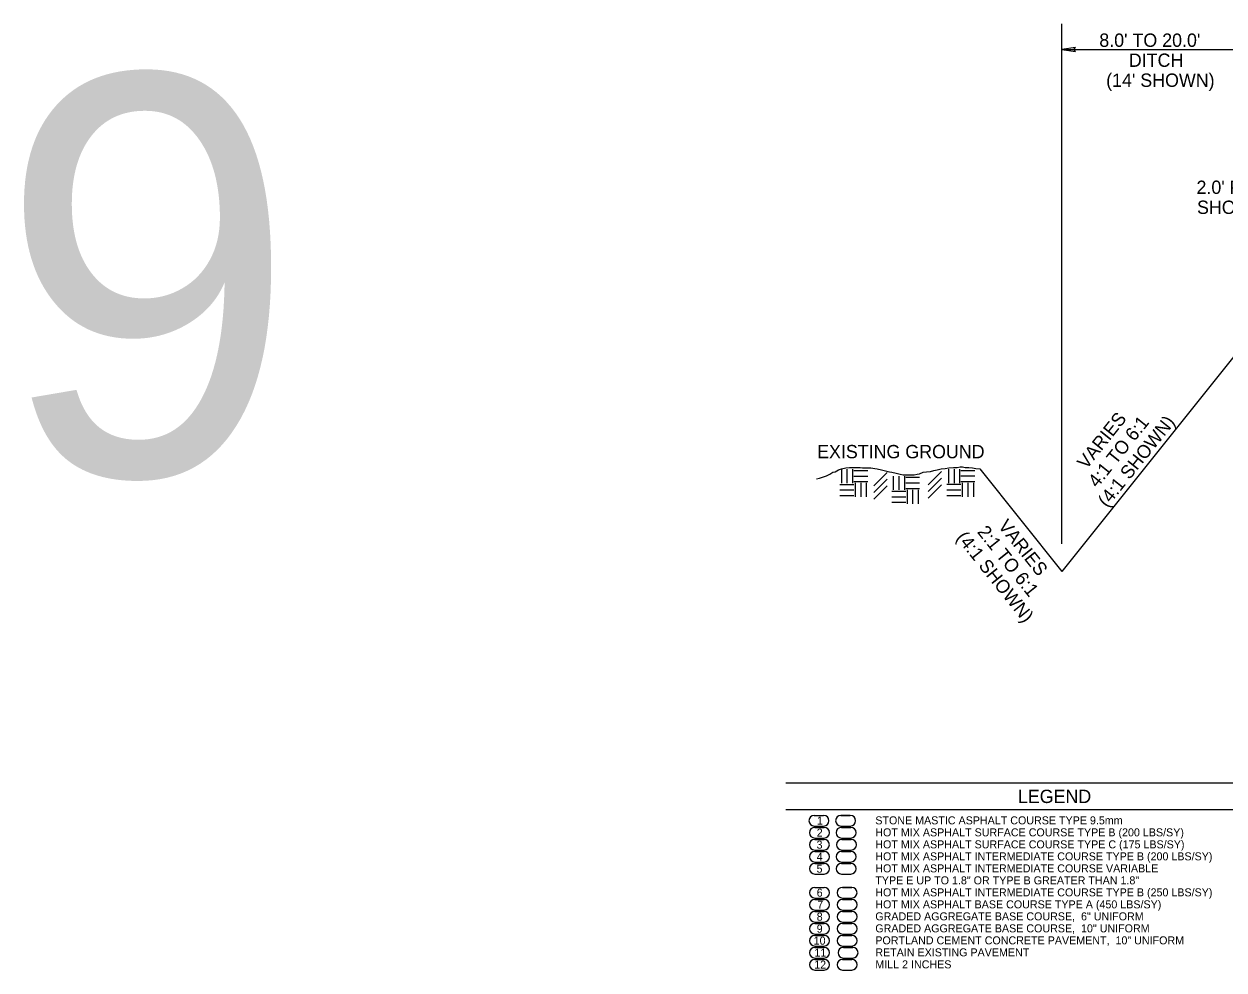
# Model space of a CAD drawing. Extents: x 2003207 to 2014043, y 843846 to 860154.
# Drawn here: x 2013558.6 to 2013648.6, y 843966.4 to 844037.3 of the extents above; entities that cross this region are included whole.
import ezdxf

# ---------------------------------------------------------------- set-up
doc = ezdxf.new("R2010")
doc.units = 0
for name, color, linetype in [('RD_EX_Road', 7, 'Continuous'), ('RD_EX_Road_txCode', 7, 'Continuous'), ('RD_QTY_ConcPave', 7, 'Continuous'), ('RD_QTY_Intermediate', 7, 'Continuous'), ('RD_QTY_Milling', 7, 'Continuous'), ('RD_QTY_PermVeg', 7, 'Continuous'), ('RD_QTY_Surf_Course', 7, 'Continuous'), ('RD_SHT_Bndy', 7, 'Continuous'), ('RD_SHT_TX', 7, 'Continuous'), ('RD_TX_Misc2', 7, 'Continuous'), ('RD_TX_TypSect', 7, 'Continuous'), ('RD_XS_ExGround', 7, 'Continuous')]:
    doc.layers.add(name, color=color, linetype=linetype)

msp = doc.modelspace()

# ---------------------------------------------------------------- linework, layer by layer
at = {"layer": 'RD_EX_Road'}
for p, q in [((2013620.723, 843968.087), (2013620.023, 843968.087)), ((2013620.661, 843967.187), (2013619.961, 843967.187)), ((2013620.023, 843967.287), (2013620.723, 843967.287)), ((2013619.961, 843966.387), (2013620.661, 843966.387))]:
    msp.add_line(p, q, dxfattribs=at)
for centre, start, end in [((2013620.023, 843967.687), 90, 270), ((2013620.723, 843967.687), 270, 90), ((2013619.961, 843966.787), 90, 270), ((2013620.661, 843966.787), 270, 90)]:
    msp.add_arc(centre, 0.4, start, end, dxfattribs=at)
at = {"layer": 'RD_EX_Road_txCode'}
msp.add_lwpolyline([(2013636.392, 844035.433), (2013637.431, 844035.283), (2013637.271, 844035.433), (2013637.431, 844035.583)], close=True, dxfattribs=at)
at = {"layer": 'RD_QTY_ConcPave'}
for p, q in [((2013620.661, 843970.787), (2013619.961, 843970.787)), ((2013619.961, 843969.987), (2013620.661, 843969.987)), ((2013620.661, 843969.887), (2013619.961, 843969.887)), ((2013619.961, 843969.087), (2013620.661, 843969.087)), ((2013620.661, 843968.987), (2013619.961, 843968.987)), ((2013619.961, 843968.187), (2013620.661, 843968.187))]:
    msp.add_line(p, q, dxfattribs=at)
for centre, start, end in [((2013619.961, 843970.387), 90, 270), ((2013620.661, 843970.387), 270, 90), ((2013619.961, 843969.487), 90, 270), ((2013620.661, 843969.487), 270, 90), ((2013619.961, 843968.587), 90, 270), ((2013620.661, 843968.587), 270, 90)]:
    msp.add_arc(centre, 0.4, start, end, dxfattribs=at)
at = {"layer": 'RD_QTY_Intermediate'}
for p, q in [((2013620.582, 843975.287), (2013619.882, 843975.287)), ((2013619.882, 843974.487), (2013620.582, 843974.487)), ((2013620.582, 843974.387), (2013619.882, 843974.387)), ((2013619.882, 843973.587), (2013620.582, 843973.587)), ((2013620.65, 843972.587), (2013619.95, 843972.587)), ((2013619.95, 843971.787), (2013620.65, 843971.787)), ((2013620.661, 843971.687), (2013619.961, 843971.687)), ((2013619.961, 843970.887), (2013620.661, 843970.887))]:
    msp.add_line(p, q, dxfattribs=at)
for centre, start, end in [((2013619.882, 843974.887), 90, 270), ((2013620.582, 843974.887), 270, 90), ((2013619.882, 843973.987), 90, 270), ((2013620.582, 843973.987), 270, 90), ((2013619.95, 843972.187), 90, 270), ((2013620.65, 843972.187), 270, 90), ((2013619.961, 843971.287), 90, 270), ((2013620.661, 843971.287), 270, 90)]:
    msp.add_arc(centre, 0.4, start, end, dxfattribs=at)
at = {"layer": 'RD_QTY_Milling'}
for p, q in [((2013620.661, 843967.187), (2013619.961, 843967.187)), ((2013619.961, 843966.387), (2013620.661, 843966.387))]:
    msp.add_line(p, q, dxfattribs=at)
for centre, start, end in [((2013619.961, 843966.787), 90, 270), ((2013620.661, 843966.787), 270, 90)]:
    msp.add_arc(centre, 0.4, start, end, dxfattribs=at)
at = {"layer": 'RD_QTY_PermVeg'}
for p in [(2013650.392, 844013.786), (2013630.245, 844003.97)]:
    msp.add_line(p, (2013636.392, 843996.286), dxfattribs=at)
at = {"layer": 'RD_QTY_Surf_Course'}
for p, q in [((2013620.542, 843977.987), (2013619.842, 843977.987)), ((2013619.842, 843977.187), (2013620.542, 843977.187)), ((2013620.576, 843977.087), (2013619.876, 843977.087)), ((2013619.876, 843976.287), (2013620.576, 843976.287)), ((2013620.61, 843976.187), (2013619.91, 843976.187)), ((2013619.91, 843975.387), (2013620.61, 843975.387))]:
    msp.add_line(p, q, dxfattribs=at)
for centre, start, end in [((2013619.842, 843977.587), 90, 270), ((2013620.542, 843977.587), 270, 90), ((2013619.876, 843976.687), 90, 270), ((2013620.576, 843976.687), 270, 90), ((2013619.91, 843975.787), 90, 270), ((2013620.61, 843975.787), 270, 90)]:
    msp.add_arc(centre, 0.4, start, end, dxfattribs=at)
at = {"layer": 'RD_SHT_Bndy'}
for p, q in [((2013655.72, 843980.41), (2013615.72, 843980.41)), ((2013655.72, 843978.41), (2013615.72, 843978.41))]:
    msp.add_line(p, q, dxfattribs=at)
at = {"layer": 'RD_TX_Misc2'}
for p, q in [((2013617.842, 843977.987), (2013618.542, 843977.987)), ((2013619.842, 843977.987), (2013620.542, 843977.987)), ((2013617.842, 843977.187), (2013618.542, 843977.187)), ((2013617.876, 843977.087), (2013618.576, 843977.087)), ((2013619.842, 843977.187), (2013620.542, 843977.187)), ((2013619.876, 843977.087), (2013620.576, 843977.087)), ((2013617.87, 843976.187), (2013618.57, 843976.187)), ((2013617.876, 843976.287), (2013618.576, 843976.287)), ((2013619.876, 843976.287), (2013620.576, 843976.287)), ((2013619.91, 843976.187), (2013620.61, 843976.187)), ((2013617.87, 843975.387), (2013618.57, 843975.387)), ((2013617.882, 843975.287), (2013618.582, 843975.287)), ((2013619.882, 843975.287), (2013620.582, 843975.287)), ((2013619.91, 843975.387), (2013620.61, 843975.387)), ((2013617.882, 843974.487), (2013618.582, 843974.487)), ((2013617.882, 843974.387), (2013618.582, 843974.387)), ((2013619.882, 843974.487), (2013620.582, 843974.487)), ((2013619.882, 843974.387), (2013620.582, 843974.387)), ((2013617.882, 843973.587), (2013618.582, 843973.587)), ((2013619.882, 843973.587), (2013620.582, 843973.587)), ((2013617.882, 843972.587), (2013618.582, 843972.587)), ((2013619.95, 843972.587), (2013620.65, 843972.587)), ((2013617.882, 843971.787), (2013618.582, 843971.787)), ((2013617.882, 843971.687), (2013618.582, 843971.687)), ((2013619.95, 843971.787), (2013620.65, 843971.787)), ((2013619.961, 843971.687), (2013620.661, 843971.687)), ((2013617.882, 843970.887), (2013618.582, 843970.887)), ((2013617.882, 843970.787), (2013618.582, 843970.787)), ((2013619.961, 843970.887), (2013620.661, 843970.887)), ((2013619.961, 843970.787), (2013620.661, 843970.787)), ((2013617.882, 843969.987), (2013618.582, 843969.987)), ((2013617.882, 843969.887), (2013618.582, 843969.887)), ((2013619.961, 843969.987), (2013620.661, 843969.987)), ((2013619.961, 843969.887), (2013620.661, 843969.887)), ((2013617.882, 843969.087), (2013618.582, 843969.087)), ((2013617.882, 843968.987), (2013618.582, 843968.987)), ((2013619.961, 843969.087), (2013620.661, 843969.087)), ((2013619.961, 843968.987), (2013620.661, 843968.987)), ((2013617.882, 843968.187), (2013618.582, 843968.187)), ((2013617.882, 843968.087), (2013618.582, 843968.087)), ((2013619.961, 843968.187), (2013620.661, 843968.187)), ((2013620.023, 843968.087), (2013620.723, 843968.087)), ((2013617.882, 843967.287), (2013618.582, 843967.287)), ((2013617.882, 843967.187), (2013618.582, 843967.187)), ((2013619.961, 843967.187), (2013620.661, 843967.187)), ((2013620.023, 843967.287), (2013620.723, 843967.287)), ((2013617.882, 843966.387), (2013618.582, 843966.387)), ((2013619.961, 843966.387), (2013620.661, 843966.387))]:
    msp.add_line(p, q, dxfattribs=at)
for centre, start, end in [((2013617.842, 843977.587), 90, 270), ((2013618.542, 843977.587), 270, 90), ((2013619.842, 843977.587), 90, 270), ((2013620.542, 843977.587), 270, 90), ((2013617.876, 843976.687), 90, 270), ((2013618.576, 843976.687), 270, 90), ((2013619.876, 843976.687), 90, 270), ((2013620.576, 843976.687), 270, 90), ((2013617.87, 843975.787), 90, 270), ((2013618.57, 843975.787), 270, 90), ((2013619.91, 843975.787), 90, 270), ((2013620.61, 843975.787), 270, 90), ((2013617.882, 843974.887), 90, 270), ((2013618.582, 843974.887), 270, 90), ((2013619.882, 843974.887), 90, 270), ((2013620.582, 843974.887), 270, 90), ((2013617.882, 843973.987), 90, 270), ((2013618.582, 843973.987), 270, 90), ((2013619.882, 843973.987), 90, 270), ((2013620.582, 843973.987), 270, 90), ((2013617.882, 843972.187), 90, 270), ((2013618.582, 843972.187), 270, 90), ((2013619.95, 843972.187), 90, 270), ((2013620.65, 843972.187), 270, 90), ((2013617.882, 843971.287), 90, 270), ((2013618.582, 843971.287), 270, 90), ((2013619.961, 843971.287), 90, 270), ((2013620.661, 843971.287), 270, 90), ((2013617.882, 843970.387), 90, 270), ((2013618.582, 843970.387), 270, 90), ((2013619.961, 843970.387), 90, 270), ((2013620.661, 843970.387), 270, 90), ((2013617.882, 843969.487), 90, 270), ((2013618.582, 843969.487), 270, 90), ((2013619.961, 843969.487), 90, 270), ((2013620.661, 843969.487), 270, 90), ((2013617.882, 843968.587), 90, 270), ((2013618.582, 843968.587), 270, 90), ((2013619.961, 843968.587), 90, 270), ((2013620.661, 843968.587), 270, 90), ((2013617.882, 843967.687), 90, 270), ((2013618.582, 843967.687), 270, 90), ((2013620.023, 843967.687), 90, 270), ((2013620.723, 843967.687), 270, 90), ((2013617.882, 843966.787), 90, 270), ((2013618.582, 843966.787), 270, 90), ((2013619.961, 843966.787), 90, 270), ((2013620.661, 843966.787), 270, 90)]:
    msp.add_arc(centre, 0.4, start, end, dxfattribs=at)
at = {"layer": 'RD_TX_TypSect'}
for p, q in [((2013636.392, 843998.341), (2013636.392, 844037.34)), ((2013636.392, 844035.433), (2013650.392, 844035.433))]:
    msp.add_line(p, q, dxfattribs=at)
at = {"layer": 'RD_XS_ExGround'}
for p, q in [((2013619.875, 844003.95), (2013619.875, 844002.908)), ((2013620.292, 844003.95), (2013620.292, 844002.908)), ((2013620.708, 844003.95), (2013620.708, 844002.908)), ((2013620.805, 844003.853), (2013621.847, 844003.853)), ((2013622.311, 844002.691), (2013623.311, 844003.691)), ((2013626.379, 844002.764), (2013627.379, 844003.764)), ((2013627.902, 844003.955), (2013627.902, 844002.913)), ((2013628.319, 844003.955), (2013628.319, 844002.913)), ((2013628.735, 844003.955), (2013628.735, 844002.913)), ((2013628.832, 844003.858), (2013629.873, 844003.858)), ((2013619.763, 844002.811), (2013620.805, 844002.811)), ((2013620.805, 844003.436), (2013621.847, 844003.436)), ((2013620.805, 844003.02), (2013621.847, 844003.02)), ((2013620.909, 844002.916), (2013620.909, 844001.874)), ((2013621.326, 844002.916), (2013621.326, 844001.874)), ((2013621.742, 844002.916), (2013621.742, 844001.874)), ((2013622.311, 844002.191), (2013623.311, 844003.191)), ((2013623.766, 844003.436), (2013623.766, 844002.395)), ((2013624.182, 844003.436), (2013624.182, 844002.395)), ((2013624.599, 844003.436), (2013624.599, 844002.395)), ((2013624.695, 844003.339), (2013625.737, 844003.339)), ((2013624.695, 844002.923), (2013625.737, 844002.923)), ((2013626.379, 844002.264), (2013627.379, 844003.264)), ((2013626.379, 844001.764), (2013627.379, 844002.764)), ((2013627.79, 844002.816), (2013628.832, 844002.816)), ((2013628.832, 844003.441), (2013629.873, 844003.441)), ((2013628.832, 844003.024), (2013629.873, 844003.024)), ((2013628.936, 844002.92), (2013628.936, 844001.879)), ((2013629.353, 844002.92), (2013629.353, 844001.879)), ((2013629.769, 844002.92), (2013629.769, 844001.879)), ((2013619.763, 844002.395), (2013620.805, 844002.395)), ((2013619.763, 844001.978), (2013620.805, 844001.978)), ((2013622.311, 844001.691), (2013623.311, 844002.691)), ((2013623.654, 844002.298), (2013624.695, 844002.298)), ((2013623.654, 844001.881), (2013624.695, 844001.881)), ((2013624.695, 844002.506), (2013625.737, 844002.506)), ((2013624.8, 844002.402), (2013624.8, 844001.36)), ((2013625.216, 844002.402), (2013625.216, 844001.36)), ((2013625.633, 844002.402), (2013625.633, 844001.36)), ((2013627.79, 844002.399), (2013628.832, 844002.399)), ((2013627.79, 844001.983), (2013628.832, 844001.983)), ((2013623.654, 844001.464), (2013624.695, 844001.464))]:
    msp.add_line(p, q, dxfattribs=at)
msp.add_lwpolyline([(2013618.019, 844003.238), (2013618.239, 844003.274), (2013618.458, 844003.348), (2013618.751, 844003.458), (2013619.008, 844003.567), (2013619.227, 844003.714), (2013619.41, 844003.751), (2013619.666, 844003.897), (2013619.886, 844003.97), (2013620.215, 844004.044), (2013620.472, 844004.08), (2013620.765, 844004.08), (2013621.094, 844004.08), (2013621.277, 844004.08), (2013621.46, 844004.044), (2013621.68, 844004.044), (2013621.899, 844004.044), (2013622.082, 844004.044), (2013622.375, 844004.007), (2013622.558, 844003.97), (2013622.888, 844003.897), (2013623.18, 844003.824), (2013623.473, 844003.751), (2013623.656, 844003.714), (2013623.986, 844003.641), (2013624.279, 844003.567), (2013624.498, 844003.531), (2013624.681, 844003.531), (2013624.901, 844003.531), (2013625.12, 844003.531), (2013625.34, 844003.531), (2013625.56, 844003.567), (2013625.743, 844003.604), (2013625.999, 844003.714), (2013626.255, 844003.751), (2013626.548, 844003.787), (2013626.804, 844003.86), (2013627.06, 844003.897), (2013627.353, 844003.97), (2013627.646, 844004.007), (2013627.939, 844004.044), (2013628.268, 844004.08), (2013628.561, 844004.08), (2013628.781, 844004.117), (2013628.964, 844004.117), (2013629.147, 844004.08), (2013629.44, 844004.08), (2013629.696, 844004.044), (2013629.952, 844004.007), (2013630.245, 844003.97)], dxfattribs=at)

# ---------------------------------------------------------------- texts
at = {"layer": 'RD_EX_Road_txCode'}
for s, height, p in [('LEGEND', 1, (2013633.11, 843978.91)), ('STONE MASTIC ASPHALT COURSE TYPE 9.5mm', 0.6, (2013622.417, 843977.31)), ('HOT MIX ASPHALT SURFACE COURSE TYPE B (200 LBS/SY)', 0.6, (2013622.417, 843976.41)), ('HOT MIX ASPHALT SURFACE COURSE TYPE C (175 LBS/SY)', 0.6, (2013622.417, 843975.51)), ('HOT MIX ASPHALT INTERMEDIATE COURSE TYPE B (200 LBS/SY)', 0.6, (2013622.417, 843974.61)), ('HOT MIX ASPHALT INTERMEDIATE COURSE VARIABLE ', 0.6, (2013622.417, 843973.71)), ('TYPE E UP TO 1.8" OR TYPE B GREATER THAN 1.8"', 0.6, (2013622.417, 843972.81)), ('HOT MIX ASPHALT INTERMEDIATE COURSE TYPE B (250 LBS/SY)', 0.6, (2013622.417, 843971.91)), ('HOT MIX ASPHALT BASE COURSE TYPE A (450 LBS/SY)', 0.6, (2013622.417, 843971.01)), ('GRADED AGGREGATE BASE COURSE,  6" UNIFORM', 0.6, (2013622.417, 843970.11)), ('GRADED AGGREGATE BASE COURSE,  10" UNIFORM', 0.6, (2013622.417, 843969.21)), ('PORTLAND CEMENT CONCRETE PAVEMENT,  10" UNIFORM', 0.6, (2013622.417, 843968.31)), ('RETAIN EXISTING PAVEMENT', 0.6, (2013622.417, 843967.41)), ('MILL 2 INCHES', 0.6, (2013622.417, 843966.51))]:
    msp.add_text(s, height=height, dxfattribs=at).set_placement(p)
at = {"layer": 'RD_SHT_TX'}
msp.add_text('9', height=30, dxfattribs=at).set_placement((2013556.7, 844003.492))
at = {"layer": 'RD_TX_Misc2'}
for s, p in [('1', (2013618.039, 843977.287)), ('2', (2013618.022, 843976.387)), ('3', (2013618.011, 843975.487)), ('4', (2013618.022, 843974.587)), ('5', (2013618.011, 843973.687)), ('6', (2013618.022, 843971.887)), ('7 ', (2013618.066, 843970.987)), ('8', (2013618.022, 843970.087)), ('9', (2013618.022, 843969.187)), ('10', (2013617.796, 843968.287)), ('11', (2013617.852, 843967.387)), ('12', (2013617.835, 843966.487))]:
    msp.add_text(s, height=0.6, dxfattribs=at).set_placement(p)
at = {"layer": 'RD_TX_TypSect'}
for s, p in [("8.0' TO 20.0'", (2013639.215, 844035.626)), ('DITCH', (2013641.428, 844034.126)), ("(14' SHOWN)", (2013639.727, 844032.626)), ("2.0' PAVED", (2013646.502, 844024.594)), ('SHOULDER', (2013646.542, 844023.094)), ('EXISTING GROUND', (2013618.053, 844004.767))]:
    msp.add_text(s, height=1, dxfattribs=at).set_placement(p)
for s, rotation, p in [('VARIES', 51.34019, (2013638.247, 844003.885)), ('4:1 TO 6:1', 51.34019, (2013639.059, 844002.5)), ('(4:1 SHOWN)', 51.34019, (2013639.798, 844001.021)), ('VARIES', 308.65981, (2013631.575, 843999.677)), ('(4:1 SHOWN)', 308.65981, (2013628.44, 843998.793)), ('2:1 TO 6:1', 308.65981, (2013630.015, 843999.226))]:
    msp.add_text(s, height=1, rotation=rotation, dxfattribs=at).set_placement(p)

doc.saveas('drawing.dxf')
